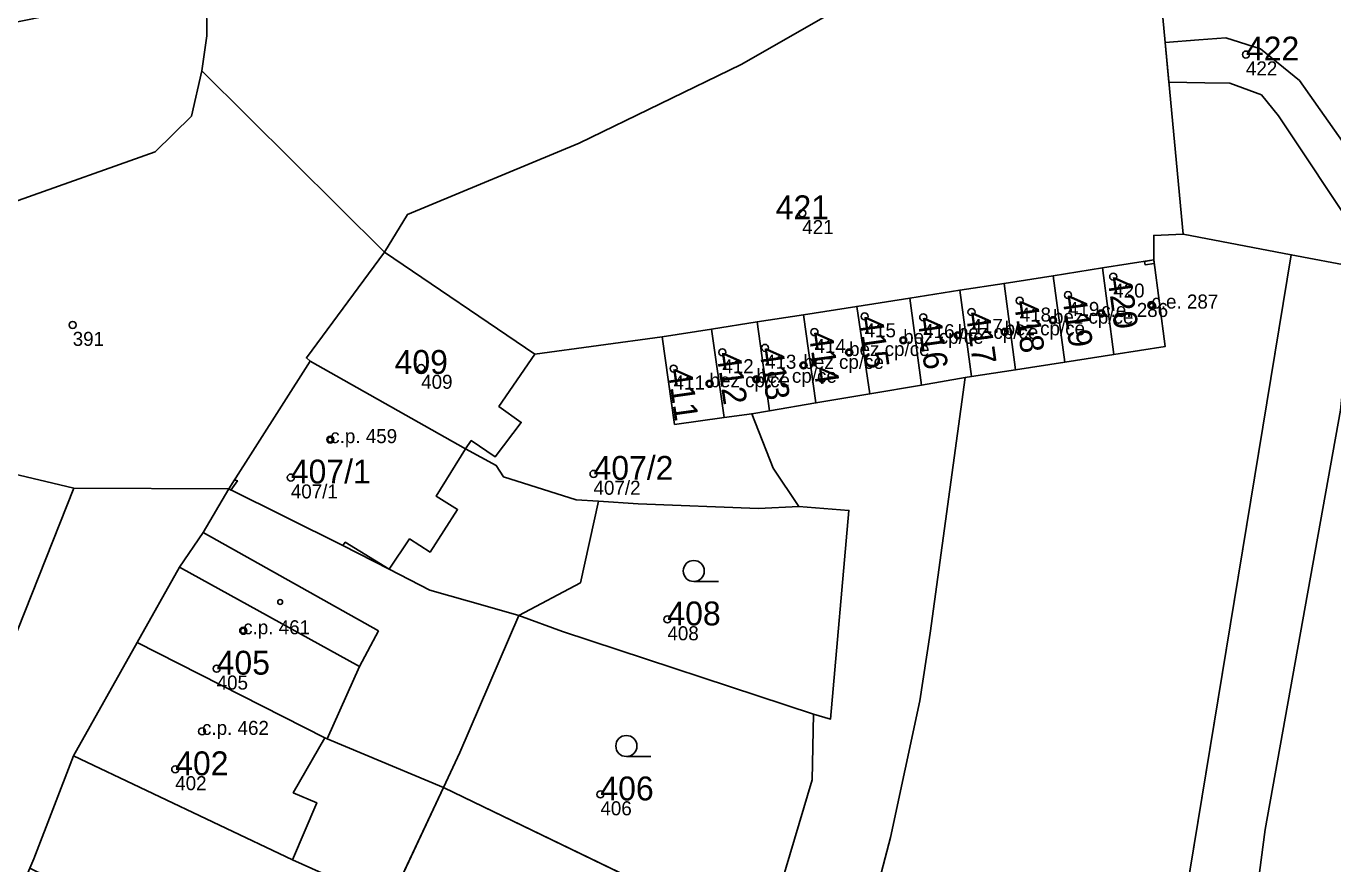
# Model space of a CAD drawing. Extents: x -878211 to -870363, y -1058464 to -1052522.
# Drawn here: x -874484.1 to -874391.1, y -1056320.4 to -1056260.7 of the extents above; entities that cross this region are included whole.
import ezdxf

# ---------------------------------------------------------------- set-up
doc = ezdxf.new("R2010")
doc.units = 0
for name, color, linetype in [('Definiční body', 7, 'Continuous'), ('Hranice parcel', 7, 'Continuous'), ('Parcelní čísla', 7, 'Continuous'), ('Polygon budovy', 7, 'Continuous'), ('Polygon parcely', 7, 'Continuous'), ('Vnitřní kresba', 7, 'Continuous'), ('Věcná břemena k části', 7, 'Continuous'), ('Značky budov', 7, 'Continuous'), ('Značky kultur', 7, 'Continuous')]:
    doc.layers.add(name, color=color, linetype=linetype)

msp = doc.modelspace()

# ---------------------------------------------------------------- linework, layer by layer
at = {"layer": 'Definiční body'}
for centre in [(-874397.27, -1056262.74994), (-874428.86, -1056274.05994), (-874406.72, -1056278.57994), (-874409.94, -1056279.88994), (-874413.38, -1056280.28994), (-874404, -1056280.59994), (-874424.42, -1056281.40994), (-874420.25, -1056281.46994), (-874416.81, -1056281.09994), (-874411.01, -1056281.67994), (-874407.57, -1056281.19994), (-874480.8, -1056282.01994), (-874427.99, -1056282.52994), (-874417.78, -1056282.75994), (-874414.45, -1056282.50994), (-874431.51, -1056283.64994), (-874421.67, -1056283.10994), (-874434.55, -1056283.96994), (-874425.52, -1056283.97994), (-874455.99, -1056285.07994), (-874438.02, -1056285.12994), (-874428.77, -1056284.89994), (-874435.46, -1056286.20994), (-874432.12, -1056285.88994), (-874462.46, -1056290.18994), (-874465.27, -1056292.88994), (-874443.72, -1056292.62994), (-874438.46, -1056302.99994), (-874468.66, -1056303.80994), (-874470.55, -1056306.50994), (-874471.59, -1056310.97994), (-874473.5, -1056313.67994), (-874443.23, -1056315.46994)]:
    msp.add_circle(centre, 0.25, dxfattribs=at)
at = {"layer": 'Hranice parcel'}
for p, q in [((-874471.6, -1056263.9), (-874458.6, -1056276.84)), ((-874401.74, -1056275.56), (-874394.05, -1056277.02)), ((-874458.6, -1056276.84), (-874447.91, -1056284.1)), ((-874394.05, -1056277.02), (-874408.81, -1056366.88)), ((-874394.05, -1056277.02), (-874389.52, -1056277.88)), ((-874407.48, -1056277.96), (-874410.99, -1056278.51)), ((-874403.83, -1056277.39), (-874407.48, -1056277.96)), ((-874406.67, -1056284.12), (-874407.48, -1056277.96)), ((-874403.02, -1056283.55), (-874403.83, -1056277.39)), ((-874410.99, -1056278.51), (-874414.49, -1056279.06)), ((-874410.17, -1056284.66), (-874410.99, -1056278.51)), ((-874417.65, -1056279.55), (-874421.21, -1056280.11)), ((-874414.49, -1056279.06), (-874417.65, -1056279.55)), ((-874416.82, -1056285.7), (-874417.65, -1056279.55)), ((-874413.67, -1056285.21), (-874414.49, -1056279.06)), ((-874424.98, -1056280.7), (-874428.76, -1056281.29)), ((-874421.21, -1056280.11), (-874424.98, -1056280.7)), ((-874424.05, -1056286.92), (-874424.98, -1056280.7)), ((-874420.36, -1056286.3), (-874421.21, -1056280.11)), ((-874428.76, -1056281.29), (-874432.07, -1056281.8)), ((-874427.89, -1056287.57), (-874428.76, -1056281.29)), ((-874435.31, -1056282.31), (-874438.83, -1056282.86)), ((-874432.07, -1056281.8), (-874435.31, -1056282.31)), ((-874434.42, -1056288.62), (-874435.31, -1056282.31)), ((-874431.19, -1056288.13), (-874432.07, -1056281.8)), ((-874447.91, -1056284.1), (-874438.83, -1056282.86)), ((-874438.83, -1056282.86), (-874437.95, -1056289.1)), ((-874406.67, -1056284.12), (-874403.02, -1056283.55)), ((-874410.17, -1056284.66), (-874406.67, -1056284.12)), ((-874463.89, -1056284.59), (-874469.69, -1056293.7)), ((-874452.83, -1056290.85), (-874463.89, -1056284.59)), ((-874416.82, -1056285.7), (-874413.67, -1056285.21)), ((-874413.67, -1056285.21), (-874410.17, -1056284.66)), ((-874424.05, -1056286.92), (-874420.36, -1056286.3)), ((-874420.36, -1056286.3), (-874417.27, -1056285.77)), ((-874417.27, -1056285.77), (-874416.82, -1056285.7)), ((-874427.89, -1056287.57), (-874424.05, -1056286.92)), ((-874432.46, -1056288.35), (-874431.19, -1056288.13)), ((-874431.19, -1056288.13), (-874427.89, -1056287.57)), ((-874437.95, -1056289.1), (-874434.42, -1056288.62)), ((-874434.42, -1056288.62), (-874432.46, -1056288.35)), ((-874469.69, -1056293.7), (-874480.72, -1056293.66)), ((-874443.37, -1056294.57), (-874444.96, -1056294.47)), ((-874443.37, -1056294.57), (-874444.64, -1056300.39)), ((-874440.55, -1056294.76), (-874443.37, -1056294.57)), ((-874444.64, -1056300.39), (-874449.03, -1056302.71)), ((-874458.27, -1056323.23), (-874454.4, -1056314.98)), ((-874431.59, -1056326), (-874454.4, -1056314.98))]:
    msp.add_line(p, q, dxfattribs=at)
for points in [[(-874401.74, -1056275.56), (-874404.75, -1056243.4), (-874396.82, -1056233.26)], [(-874408.34, -1056241.77), (-874422.29, -1056256.77), (-874426.85, -1056259.82), (-874433.2, -1056263.45), (-874444.74, -1056269.07), (-874456.97, -1056274.14), (-874458.6, -1056276.84)], [(-874471.6, -1056263.9), (-874471.26, -1056261.41), (-874471.27, -1056258.91)], [(-874403.83, -1056277.39), (-874403.83, -1056275.64), (-874401.74, -1056275.56)], [(-874463.89, -1056284.59), (-874464.16, -1056284.37), (-874458.6, -1056276.84)], [(-874452.83, -1056290.85), (-874452.43, -1056290.26), (-874450.73, -1056291.42), (-874448.86, -1056288.96), (-874450.45, -1056287.82), (-874447.91, -1056284.1)], [(-874417.27, -1056285.77), (-874419.76, -1056303.99), (-874420.48, -1056308.81), (-874422.58, -1056318.54), (-874433.58, -1056360.58)], [(-874402.03, -1056368.61), (-874398.91, -1056340.89), (-874395.91, -1056317.97), (-874390.55, -1056288.09)], [(-874432.46, -1056288.35), (-874430.92, -1056292.23), (-874429.1, -1056294.96)], [(-874444.96, -1056294.47), (-874450.14, -1056292.83), (-874450.65, -1056292.03), (-874452.83, -1056290.85)], [(-874476.21, -1056304.64), (-874473.19, -1056299.28), (-874471.52, -1056296.81), (-874469.69, -1056293.7)], [(-874469.69, -1056293.7), (-874461.57, -1056297.74), (-874458.28, -1056299.42), (-874455.37, -1056300.91), (-874451.28, -1056302.07), (-874449.03, -1056302.71)], [(-874429.1, -1056294.96), (-874431.97, -1056295.09), (-874440.55, -1056294.76)], [(-874428.05, -1056309.75), (-874426.84, -1056310.1), (-874425.54, -1056295.23), (-874429.1, -1056294.96)], [(-874454.4, -1056314.98), (-874453.23, -1056312.49), (-874449.03, -1056302.71)], [(-874449.03, -1056302.71), (-874445.92, -1056303.86), (-874428.05, -1056309.75)], [(-874454.4, -1056314.98), (-874460.07, -1056312.6), (-874462.69, -1056311.5), (-874462.85, -1056311.43), (-874476.21, -1056304.64)], [(-874428.05, -1056309.75), (-874428.16, -1056314.44), (-874431.59, -1056326)], [(-874458.27, -1056323.23), (-874465.16, -1056320.12), (-874480.74, -1056312.73)]]:
    msp.add_lwpolyline(points, dxfattribs=at)
at = {"layer": 'Polygon budovy'}
for points in [[(-874410.99, -1056278.51), (-874410.17, -1056284.66), (-874406.67, -1056284.12), (-874407.48, -1056277.96)], [(-874407.48, -1056277.96), (-874406.67, -1056284.12), (-874403.02, -1056283.55), (-874403.83, -1056277.39)], [(-874414.49, -1056279.06), (-874413.67, -1056285.21), (-874410.17, -1056284.66), (-874410.99, -1056278.51)], [(-874421.21, -1056280.11), (-874420.36, -1056286.3), (-874417.27, -1056285.77), (-874416.82, -1056285.7), (-874417.65, -1056279.55)], [(-874417.65, -1056279.55), (-874416.82, -1056285.7), (-874413.67, -1056285.21), (-874414.49, -1056279.06)], [(-874428.76, -1056281.29), (-874427.89, -1056287.57), (-874424.05, -1056286.92), (-874424.98, -1056280.7)], [(-874424.98, -1056280.7), (-874424.05, -1056286.92), (-874420.36, -1056286.3), (-874421.21, -1056280.11)], [(-874432.07, -1056281.8), (-874431.19, -1056288.13), (-874427.89, -1056287.57), (-874428.76, -1056281.29)], [(-874438.83, -1056282.86), (-874437.95, -1056289.1), (-874434.42, -1056288.62), (-874435.31, -1056282.31)], [(-874435.31, -1056282.31), (-874434.42, -1056288.62), (-874432.46, -1056288.35), (-874431.19, -1056288.13), (-874432.07, -1056281.8)], [(-874463.89, -1056284.59), (-874469.69, -1056293.7), (-874461.57, -1056297.74), (-874461.4, -1056297.5), (-874458.28, -1056299.42), (-874456.82, -1056297.27), (-874455.35, -1056298.2), (-874453.4, -1056295.18), (-874454.93, -1056294.21), (-874452.83, -1056290.85)], [(-874496.23, -1056304.13), (-874495.84, -1056304.27), (-874486.23, -1056307.5), (-874480.72, -1056293.66), (-874491.02, -1056291.19), (-874492.6, -1056295.09), (-874494.26, -1056294.49), (-874496.02, -1056298.76), (-874494.35, -1056299.44), (-874495.42, -1056302.11)], [(-874473.19, -1056299.28), (-874476.21, -1056304.64), (-874462.85, -1056311.43), (-874462.69, -1056311.5), (-874460.37, -1056306.35)], [(-874476.21, -1056304.64), (-874480.74, -1056312.73), (-874465.16, -1056320.12), (-874463.43, -1056316.06), (-874465.1, -1056315.35), (-874462.85, -1056311.43)]]:
    msp.add_lwpolyline(points, close=True, dxfattribs=at)
at = {"layer": 'Polygon parcely'}
for points in [[(-874401.74, -1056275.56), (-874394.05, -1056277.02), (-874389.52, -1056277.88), (-874389.3, -1056275.73), (-874387.64, -1056259.25), (-874387.97, -1056254.06), (-874388.99, -1056251.4), (-874390.11, -1056248.75), (-874396.41, -1056249.4), (-874396.7, -1056237.81), (-874396.82, -1056233.26), (-874404.75, -1056243.4)], [(-874507.34, -1056279.88), (-874484.69, -1056273.16), (-874474.92, -1056269.69), (-874472.35, -1056267.13), (-874471.6, -1056263.9), (-874471.26, -1056261.41), (-874471.27, -1056258.91), (-874471.42, -1056257.72), (-874502.78, -1056264.06), (-874511.26, -1056267.37)], [(-874408.81, -1056366.88), (-874394.05, -1056277.02), (-874401.74, -1056275.56), (-874403.83, -1056275.64), (-874403.83, -1056277.39), (-874403.02, -1056283.55), (-874406.67, -1056284.12), (-874410.17, -1056284.66), (-874413.67, -1056285.21), (-874416.82, -1056285.7), (-874417.27, -1056285.77), (-874419.76, -1056303.99), (-874420.48, -1056308.81), (-874422.58, -1056318.54), (-874433.58, -1056360.58)], [(-874452.43, -1056290.26), (-874450.73, -1056291.42), (-874448.86, -1056288.96), (-874450.45, -1056287.82), (-874447.91, -1056284.1), (-874458.6, -1056276.84), (-874464.16, -1056284.37), (-874463.89, -1056284.59), (-874452.83, -1056290.85)], [(-874402.03, -1056368.61), (-874398.91, -1056340.89), (-874395.91, -1056317.97), (-874390.55, -1056288.09), (-874389.52, -1056277.88), (-874394.05, -1056277.02), (-874408.81, -1056366.88)], [(-874407.48, -1056277.96), (-874410.99, -1056278.51), (-874410.17, -1056284.66), (-874406.67, -1056284.12)], [(-874403.83, -1056277.39), (-874407.48, -1056277.96), (-874406.67, -1056284.12), (-874403.02, -1056283.55)], [(-874396.34, -1056370.15), (-874384.87, -1056291.52), (-874382.69, -1056279.17), (-874389.52, -1056277.88), (-874390.55, -1056288.09), (-874395.91, -1056317.97), (-874398.91, -1056340.89), (-874402.03, -1056368.61)], [(-874413.67, -1056285.21), (-874410.17, -1056284.66), (-874410.99, -1056278.51), (-874414.49, -1056279.06)], [(-874417.27, -1056285.77), (-874416.82, -1056285.7), (-874417.65, -1056279.55), (-874421.21, -1056280.11), (-874420.36, -1056286.3)], [(-874413.67, -1056285.21), (-874414.49, -1056279.06), (-874417.65, -1056279.55), (-874416.82, -1056285.7)], [(-874427.89, -1056287.57), (-874424.05, -1056286.92), (-874424.98, -1056280.7), (-874428.76, -1056281.29)], [(-874421.21, -1056280.11), (-874424.98, -1056280.7), (-874424.05, -1056286.92), (-874420.36, -1056286.3)], [(-874428.76, -1056281.29), (-874432.07, -1056281.8), (-874431.19, -1056288.13), (-874427.89, -1056287.57)], [(-874434.42, -1056288.62), (-874435.31, -1056282.31), (-874438.83, -1056282.86), (-874437.95, -1056289.1)], [(-874432.46, -1056288.35), (-874431.19, -1056288.13), (-874432.07, -1056281.8), (-874435.31, -1056282.31), (-874434.42, -1056288.62)], [(-874440.55, -1056294.76), (-874431.97, -1056295.09), (-874429.1, -1056294.96), (-874430.92, -1056292.23), (-874432.46, -1056288.35), (-874434.42, -1056288.62), (-874437.95, -1056289.1), (-874438.83, -1056282.86), (-874447.91, -1056284.1), (-874450.45, -1056287.82), (-874448.86, -1056288.96), (-874450.73, -1056291.42), (-874452.43, -1056290.26), (-874452.83, -1056290.85), (-874450.65, -1056292.03), (-874450.14, -1056292.83), (-874444.96, -1056294.47), (-874443.37, -1056294.57)], [(-874450.65, -1056292.03), (-874452.83, -1056290.85), (-874463.89, -1056284.59), (-874469.69, -1056293.7), (-874461.57, -1056297.74), (-874458.28, -1056299.42), (-874455.37, -1056300.91), (-874451.28, -1056302.07), (-874449.03, -1056302.71), (-874444.64, -1056300.39), (-874443.37, -1056294.57), (-874444.96, -1056294.47), (-874450.14, -1056292.83)], [(-874428.05, -1056309.75), (-874428.16, -1056314.44), (-874431.59, -1056326), (-874434.69, -1056333.9), (-874437.8, -1056343.65), (-874442.52, -1056358.05), (-874433.58, -1056360.58), (-874422.58, -1056318.54), (-874420.48, -1056308.81), (-874419.76, -1056303.99), (-874417.27, -1056285.77), (-874420.36, -1056286.3), (-874424.05, -1056286.92), (-874427.89, -1056287.57), (-874431.19, -1056288.13), (-874432.46, -1056288.35), (-874430.92, -1056292.23), (-874429.1, -1056294.96), (-874425.54, -1056295.23), (-874426.84, -1056310.1)], [(-874495.42, -1056302.11), (-874496.23, -1056304.13), (-874495.84, -1056304.27), (-874486.23, -1056307.5), (-874480.72, -1056293.66), (-874491.02, -1056291.19), (-874492.6, -1056295.09), (-874494.26, -1056294.49), (-874496.02, -1056298.76), (-874494.35, -1056299.44)], [(-874453.23, -1056312.49), (-874449.03, -1056302.71), (-874451.28, -1056302.07), (-874455.37, -1056300.91), (-874458.28, -1056299.42), (-874461.57, -1056297.74), (-874469.69, -1056293.7), (-874471.52, -1056296.81), (-874473.19, -1056299.28), (-874476.21, -1056304.64), (-874462.85, -1056311.43), (-874462.69, -1056311.5), (-874460.07, -1056312.6), (-874454.4, -1056314.98)], [(-874440.55, -1056294.76), (-874443.37, -1056294.57), (-874444.64, -1056300.39), (-874449.03, -1056302.71), (-874445.92, -1056303.86), (-874428.05, -1056309.75), (-874426.84, -1056310.1), (-874425.54, -1056295.23), (-874429.1, -1056294.96), (-874431.97, -1056295.09)], [(-874428.05, -1056309.75), (-874445.92, -1056303.86), (-874449.03, -1056302.71), (-874453.23, -1056312.49), (-874454.4, -1056314.98), (-874431.59, -1056326), (-874428.16, -1056314.44)], [(-874462.69, -1056311.5), (-874462.85, -1056311.43), (-874476.21, -1056304.64), (-874480.74, -1056312.73), (-874465.16, -1056320.12), (-874458.27, -1056323.23), (-874454.4, -1056314.98), (-874460.07, -1056312.6)], [(-874434.69, -1056333.9), (-874458.27, -1056323.23), (-874465.16, -1056320.12), (-874480.74, -1056312.73), (-874483.57, -1056320.05), (-874483.86, -1056320.72), (-874470.58, -1056327.23), (-874465.27, -1056330.21), (-874460.83, -1056332.49), (-874459.33, -1056333.22), (-874437.8, -1056343.65)], [(-874431.59, -1056326), (-874454.4, -1056314.98), (-874458.27, -1056323.23), (-874434.69, -1056333.9)]]:
    msp.add_lwpolyline(points, close=True, dxfattribs=at)
for points in [[(-874426.85, -1056259.82), (-874433.2, -1056263.45), (-874444.74, -1056269.07), (-874456.97, -1056274.14), (-874458.6, -1056276.84), (-874447.91, -1056284.1), (-874438.83, -1056282.86), (-874435.31, -1056282.31), (-874432.07, -1056281.8), (-874428.76, -1056281.29), (-874424.98, -1056280.7), (-874421.21, -1056280.11), (-874417.65, -1056279.55), (-874414.49, -1056279.06), (-874410.99, -1056278.51), (-874407.48, -1056277.96), (-874403.83, -1056277.39), (-874403.83, -1056275.64), (-874401.74, -1056275.56), (-874404.75, -1056243.4)], [(-874471.27, -1056258.91), (-874471.26, -1056261.41), (-874471.6, -1056263.9), (-874458.6, -1056276.84), (-874456.97, -1056274.14), (-874444.74, -1056269.07), (-874433.2, -1056263.45), (-874426.85, -1056259.82)], [(-874491.02, -1056291.19), (-874480.72, -1056293.66), (-874469.69, -1056293.7), (-874463.89, -1056284.59), (-874464.16, -1056284.37), (-874458.6, -1056276.84), (-874471.6, -1056263.9), (-874472.35, -1056267.13), (-874474.92, -1056269.69), (-874484.69, -1056273.16)], [(-874486.75, -1056327.55), (-874483.86, -1056320.72), (-874483.57, -1056320.05), (-874480.74, -1056312.73), (-874476.21, -1056304.64), (-874473.19, -1056299.28), (-874471.52, -1056296.81), (-874469.69, -1056293.7), (-874480.72, -1056293.66), (-874486.23, -1056307.5)]]:
    msp.add_lwpolyline(points, dxfattribs=at)
at = {"layer": 'Vnitřní kresba'}
for p, q in [((-874454.93, -1056294.21), (-874452.83, -1056290.85)), ((-874453.4, -1056295.18), (-874454.93, -1056294.21)), ((-874455.35, -1056298.2), (-874453.4, -1056295.18)), ((-874459.02, -1056303.81), (-874471.52, -1056296.81)), ((-874461.57, -1056297.74), (-874461.4, -1056297.5)), ((-874461.4, -1056297.5), (-874458.28, -1056299.42)), ((-874458.28, -1056299.42), (-874456.82, -1056297.27)), ((-874456.82, -1056297.27), (-874455.35, -1056298.2)), ((-874473.19, -1056299.28), (-874460.37, -1056306.35)), ((-874460.37, -1056306.35), (-874459.02, -1056303.81)), ((-874462.69, -1056311.5), (-874460.37, -1056306.35)), ((-874465.1, -1056315.35), (-874462.85, -1056311.43)), ((-874465.16, -1056320.12), (-874463.43, -1056316.06)), ((-874463.43, -1056316.06), (-874465.1, -1056315.35))]:
    msp.add_line(p, q, dxfattribs=at)
at = {"layer": 'Věcná břemena k části'}
for points in [[(-874398.41, -1056264.78), (-874396.17, -1056265.62), (-874394.96, -1056267.12), (-874389.29, -1056275.65), (-874388.84, -1056271.15), (-874388.92, -1056271.04), (-874393.47, -1056264.59), (-874396.23, -1056262.35), (-874398.71, -1056261.55), (-874400.63, -1056261.7), (-874403.02, -1056261.89), (-874402.75, -1056264.73), (-874400.19, -1056264.76)], [(-874403.8, -1056277.65), (-874403.83, -1056277.39), (-874404.49, -1056277.49), (-874404.45, -1056277.73)], [(-874469.28, -1056293.06), (-874469.69, -1056293.7), (-874469.54, -1056293.78), (-874469.07, -1056293.12)]]:
    msp.add_lwpolyline(points, close=True, dxfattribs=at)
at = {"layer": 'Značky budov'}
for centre in [(-874404.0068, -1056280.59916), (-874411.0168, -1056281.67916), (-874407.5768, -1056281.19916), (-874417.7868, -1056282.75916), (-874414.4568, -1056282.50916), (-874421.6768, -1056283.10916), (-874425.5268, -1056283.97916), (-874428.7768, -1056284.89916), (-874435.4668, -1056286.20916), (-874432.1268, -1056285.88916), (-874462.4668, -1056290.18916), (-874466.0268, -1056301.75916), (-874468.6668, -1056303.80916)]:
    msp.add_circle(centre, 0.175, dxfattribs=at)
at = {"layer": 'Značky kultur'}
for p, q in [((-874436.583, -1056300.3), (-874434.833, -1056300.3)), ((-874441.383, -1056312.77), (-874439.633, -1056312.77))]:
    msp.add_line(p, q, dxfattribs=at)
for centre in [(-874436.58286, -1056299.54981), (-874441.38286, -1056312.01981)]:
    msp.add_circle(centre, 0.75, dxfattribs=at)

# ---------------------------------------------------------------- texts
at = {"layer": 'Definiční body'}
for s, p in [('422', (-874397.27, -1056264.239)), ('421', (-874428.86, -1056275.549)), ('420', (-874406.72, -1056280.069)), ('c.e. 287', (-874404, -1056280.85)), ('418', (-874413.38, -1056281.779)), ('419', (-874409.94, -1056281.379)), ('c.e. 286', (-874407.57, -1056281.45)), ('417', (-874416.81, -1056282.589)), ('bez cp/ce', (-874414.45, -1056282.76)), ('bez cp/ce', (-874411.01, -1056281.929)), ('391', (-874480.8, -1056283.509)), ('415', (-874424.42, -1056282.899)), ('bez cp/ce', (-874421.67, -1056283.36)), ('416', (-874420.25, -1056282.959)), ('bez cp/ce', (-874417.78, -1056283.01)), ('414', (-874427.99, -1056284.019)), ('bez cp/ce', (-874425.52, -1056284.23)), ('412', (-874434.55, -1056285.459)), ('413', (-874431.51, -1056285.139)), ('bez cp/ce', (-874428.77, -1056285.149)), ('bez cp/ce', (-874435.46, -1056286.46)), ('bez cp/ce', (-874432.12, -1056286.139)), ('409', (-874455.99, -1056286.569)), ('411', (-874438.02, -1056286.619)), ('c.p. 459', (-874462.46, -1056290.44)), ('407/1', (-874465.27, -1056294.379)), ('407/2', (-874443.72, -1056294.119)), ('c.p. 461', (-874468.66, -1056304.06)), ('408', (-874438.46, -1056304.489)), ('405', (-874470.55, -1056307.999)), ('c.p. 462', (-874471.59, -1056311.23)), ('402', (-874473.5, -1056315.169)), ('406', (-874443.23, -1056316.959))]:
    msp.add_text(s, height=0.999996, dxfattribs=at).set_placement(p)
at = {"layer": 'Parcelní čísla'}
for s, p in [('422', (-874397.27, -1056263.175)), ('421', (-874430.75, -1056274.485)), ('409', (-874457.88, -1056285.505)), ('407/1', (-874465.27, -1056293.314)), ('407/2', (-874443.72, -1056293.054)), ('408', (-874438.46, -1056303.425)), ('405', (-874470.55, -1056306.935)), ('402', (-874473.5, -1056314.104)), ('406', (-874443.23, -1056315.895))]:
    msp.add_text(s, height=1.699998, dxfattribs=at).set_placement(p)
for s, p in [('420', (-874407.14, -1056278.639)), ('418', (-874413.8, -1056280.349)), ('419', (-874410.36, -1056279.949)), ('415', (-874424.84, -1056281.469)), ('416', (-874420.67, -1056281.529)), ('417', (-874417.23, -1056281.159)), ('414', (-874428.41, -1056282.589)), ('412', (-874434.97, -1056284.029)), ('413', (-874431.93, -1056283.709)), ('411', (-874438.44, -1056285.189))]:
    msp.add_text(s, height=1.699998, rotation=278, dxfattribs=at).set_placement(p)

doc.saveas('drawing.dxf')
